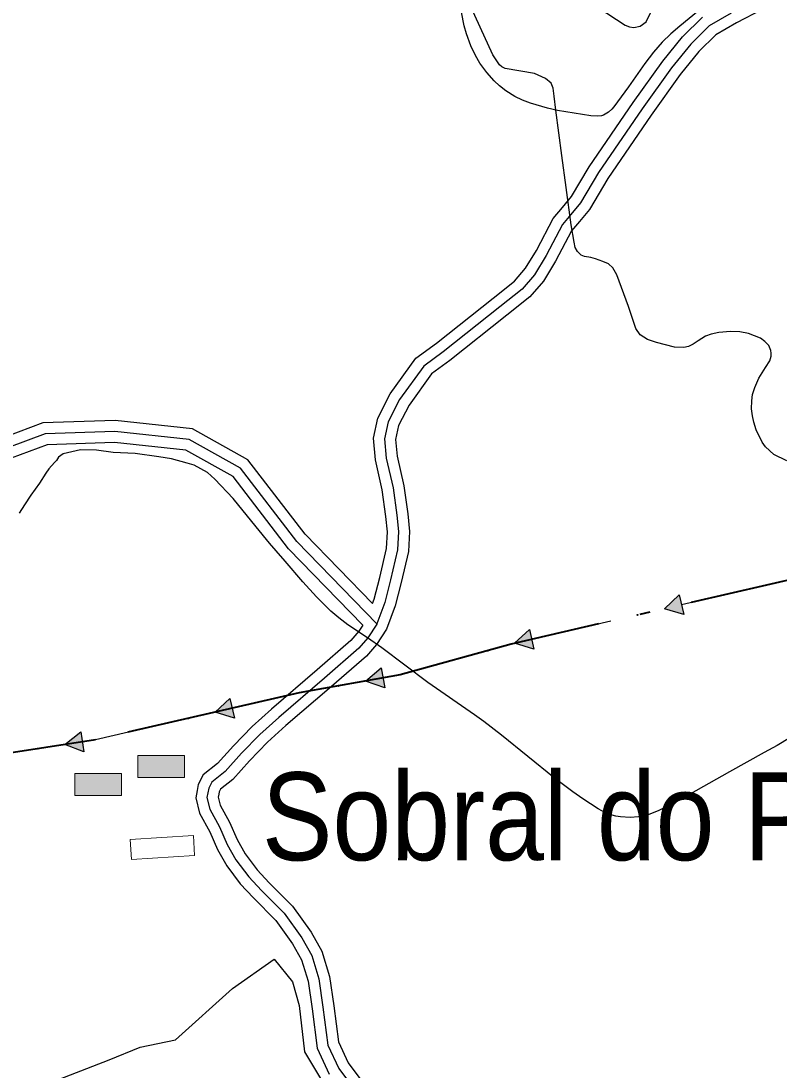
# Model space of a CAD drawing. Extents: x -64005 to -55000, y -89025 to -80000.
# Drawn here: x -60437 to -59747, y -83126 to -82170 of the extents above; entities that cross this region are included whole.
import ezdxf
from ezdxf.enums import TextEntityAlignment as Align

# ---------------------------------------------------------------- set-up
doc = ezdxf.new("R2010")
doc.units = 0
doc.header["$LTSCALE"] = 32
doc.linetypes.add('DOT_DASHED', pattern=[7.7, 5, -1.2, 0.3, -1.2])
doc.linetypes.add('LONG_DASHED', pattern=[7.5, 6, -1.5])
for name, color, linetype, lineweight in [('18', 7, 'Continuous', 25), ('24', 7, 'Continuous', 25), ('39', 7, 'LONG_DASHED', 25), ('7', 7, 'Continuous', 13), ('8', 7, 'Continuous', 25)]:
    doc.layers.add(name, color=color, linetype=linetype, lineweight=lineweight)
doc.layers.add('45', color=7, linetype='Continuous')

msp = doc.modelspace()

# ---------------------------------------------------------------- hatches: boundary and pattern name
at = {"layer": '18'}
for points in [[(-59833.76, -82710.63), (-59851.45, -82705.23), (-59837.92, -82692.61)], [(-59970.17, -82742.14), (-59987.86, -82736.73), (-59974.33, -82724.11)], [(-60106.08, -82777.3), (-60123.49, -82771.03), (-60109.35, -82759.1)], [(-60242.84, -82804.89), (-60260.53, -82799.46), (-60246.98, -82786.86)], [(-60380.13, -82835.48), (-60397.37, -82828.75), (-60382.93, -82817.19)]]:
    msp.add_hatch(color=256, dxfattribs=at).paths.add_polyline_path(points)
at = {"layer": '7'}
for points in [[(-60288.31, -82838.97), (-60330.81, -82838.97), (-60330.81, -82858.97), (-60288.31, -82858.97)], [(-60345.88, -82855.27), (-60388.38, -82855.27), (-60388.38, -82875.27), (-60345.88, -82875.27)]]:
    msp.add_hatch(color=256, dxfattribs=at).paths.add_polyline_path(points)

# ---------------------------------------------------------------- linework, layer by layer
at = {"layer": '18'}
for p, q in [((-59763.76, -82684.97), (-59835.84, -82701.62)), ((-59900.17, -82716.48), (-59972.25, -82733.12))]:
    msp.add_line(p, q, dxfattribs=at)
at = {"layer": '18', "linetype": 'DOT_DASHED', "lineweight": 40}
msp.add_lwpolyline([(-59415, -82487.84), (-59547.04, -82633.44), (-59552.52, -82637.79), (-59671.25, -82663.61), (-59990.81, -82737.41), (-60092.11, -82765.4), (-60184.07, -82781.9), (-60369.54, -82824.5), (-60744.45, -82882.06)], dxfattribs=at)
at = {"layer": '18'}
for points in [[(-59833.76, -82710.63), (-59851.45, -82705.23), (-59837.92, -82692.61)], [(-59970.17, -82742.14), (-59987.86, -82736.73), (-59974.33, -82724.11)], [(-60106.08, -82777.3), (-60123.49, -82771.03), (-60109.35, -82759.1)], [(-60242.84, -82804.89), (-60260.53, -82799.46), (-60246.98, -82786.86)], [(-60380.13, -82835.48), (-60397.37, -82828.75), (-60382.93, -82817.19)]]:
    msp.add_lwpolyline(points, close=True, dxfattribs=at)
for points in [[(-60036.09, -82749.92), (-60092.11, -82765.4), (-60107.72, -82768.2)], [(-60172.7, -82779.86), (-60184.07, -82781.9), (-60244.91, -82795.87)], [(-60309.26, -82810.65), (-60369.54, -82824.5), (-60381.53, -82826.33)]]:
    msp.add_lwpolyline(points, dxfattribs=at)
for centre in [(-59875.81, -82710.85), (-60011.99, -82743.26), (-60148.09, -82775.45), (-60284.89, -82805.06), (-60422.08, -82832.53)]:
    msp.add_circle(centre, 0.5, dxfattribs=at)
at = {"layer": '24'}
msp.add_lwpolyline([(-59820.41, -82161.05), (-59837.35, -82174.85), (-59845.51, -82181.99), (-59853.29, -82189.56), (-59861.23, -82198.55), (-59869.17, -82208.88), (-59884.17, -82230.19), (-59897.5, -82248.39), (-59899.25, -82250.46), (-59902.31, -82253.29), (-59906.86, -82255.9), (-59908.73, -82256.48), (-59912.56, -82257.02), (-59918.43, -82256.66), (-59948.62, -82251.64), (-59957.84, -82249.55), (-59973.2, -82245.1), (-59980.53, -82242.32), (-59987.66, -82238.92), (-59995.77, -82233.89), (-60001.44, -82229.43), (-60006.47, -82224.69), (-60013.15, -82217.21), (-60019.36, -82208.69), (-60023.5, -82201.72), (-60027.74, -82192.84), (-60031.66, -82181.96), (-60033.65, -82174.61), (-60036.09, -82162.18)], dxfattribs=at)
at = {"layer": '39'}
for points in [[(-59790.53, -82163.21), (-59810.54, -82174.76), (-59827.44, -82191.38), (-59844.91, -82212.8), (-59871.66, -82250.26), (-59911.37, -82308.29), (-59927.71, -82335.9), (-59936.45, -82346.33), (-59944.34, -82355.62), (-59958.99, -82383.79)], [(-59958.99, -82383.79), (-59969.69, -82401.26), (-59980.96, -82414.22), (-60001.24, -82430.29), (-60052.78, -82471.42), (-60070.54, -82484.38), (-60092.51, -82514.81), (-60102.94, -82535.09), (-60106.32, -82550.58), (-60104.63, -82568.04), (-60098.43, -82595.08), (-60095.05, -82620.15), (-60093.64, -82635.08), (-60094.48, -82651.7), (-60100.96, -82679.02), (-60106.03, -82699.59), (-60113.2, -82718.88)], [(-60113.2, -82718.88), (-60186.18, -82644.05), (-60237.35, -82577.3), (-60284.06, -82551.23), (-60351.91, -82543.94), (-60415.31, -82546.03), (-60448.68, -82558.55), (-60477.6, -82562.73), (-60498.07, -82569.45)], [(-60113.2, -82718.88), (-60113.36, -82719.3), (-60121.53, -82731.7), (-60129.69, -82741.28), (-60160.95, -82768.34), (-60202.65, -82804.12), (-60219.83, -82819.61), (-60236.45, -82836.79), (-60251.37, -82853.42), (-60263.49, -82863), (-60266.3, -82868.63), (-60267.99, -82877.08), (-60265.46, -82887.79), (-60256.45, -82903.84), (-60249.4, -82919.9), (-60241.52, -82933.7), (-60229.97, -82949.18), (-60218.42, -82961.57), (-60197.58, -82982.42), (-60181.52, -83004.95), (-60172.51, -83021.01), (-60166.03, -83042.13), (-60162.37, -83068.05), (-60157.86, -83102.41), (-60148, -83123.82), (-60136.45, -83139.31)]]:
    msp.add_lwpolyline(points, dxfattribs=at)
at = {"layer": '7', "lineweight": 25}
for points in [[(-59945.03, -82135.71), (-59887.11, -82173.96), (-59883.25, -82175.62), (-59879.2, -82176.17), (-59873.32, -82174.88), (-59867.99, -82171.02), (-59846.48, -82126.5)], [(-59754.16, -82472.65), (-59754.35, -82470.26), (-59756.37, -82465.66), (-59759.86, -82461.98), (-59763.91, -82459.04), (-59774.94, -82454.81), (-59782.85, -82453.16), (-59791.3, -82452.79), (-59801.97, -82453.71), (-59808.95, -82455.18), (-59814.1, -82457.21), (-59820.53, -82461.44), (-59825.13, -82464.57), (-59829.54, -82466.41), (-59833.59, -82467.51), (-59842.23, -82467.14), (-59858.59, -82462.92), (-59866.68, -82460.16), (-59873.48, -82455.93), (-59877.34, -82450.23), (-59884.15, -82429.99), (-59894.82, -82401.3), (-59898.3, -82395.05), (-59902.35, -82391.37), (-59907.31, -82389.17), (-59914.11, -82386.78), (-59918.53, -82385.67), (-59924.04, -82384.75), (-59927.17, -82383.47), (-59930.66, -82379.97), (-59932.68, -82376.48), (-59933.6, -82371.7), (-59936.18, -82355.88), (-59940.78, -82321.85), (-59944.82, -82292.61), (-59950.16, -82251.41), (-59951.82, -82238.71), (-59952.73, -82231.36), (-59954.57, -82226.94), (-59959.54, -82222.71), (-59969.65, -82218.12), (-59996.31, -82213.52), (-59999.43, -82211.87), (-60001.64, -82210.03), (-60007.53, -82201.02), (-60030.7, -82150.44)], [(-59739.82, -82570.68), (-59751.77, -82564.8), (-59759.31, -82557.99), (-59762.25, -82553.58), (-59767.95, -82542.54), (-59769.97, -82535.55), (-59771.26, -82529.67), (-59772, -82523.41), (-59771.81, -82516.06), (-59771.08, -82510.17), (-59769.06, -82503.73), (-59765.38, -82495.27), (-59759.32, -82485.52), (-59755.45, -82479.46), (-59754.16, -82475.41), (-59754.16, -82472.65)], [(-60204.9, -82652.61), (-60211.11, -82645.41), (-60223, -82630.64), (-60244.09, -82604.94), (-60260.92, -82587.3), (-60267.56, -82581.33), (-60273.57, -82577.76), (-60279.63, -82574.62), (-60285.9, -82572.74), (-60300.22, -82568.7), (-60311.68, -82566.85), (-60333.38, -82564.05), (-60353.49, -82562.99), (-60368.52, -82561.06), (-60383.21, -82560.59), (-60399.04, -82564.1), (-60403.02, -82567.37), (-60405.01, -82570.36), (-60406.82, -82572.16), (-60411.84, -82577.85), (-60414.57, -82581.7), (-60420.57, -82590.92), (-60428.43, -82601.9), (-60434.11, -82610.63), (-60439.05, -82618.21)], [(-59725.79, -82815.8), (-59748.81, -82829.62), (-59760.44, -82836.09), (-59792.21, -82853.66), (-59834.46, -82877.64), (-59856.99, -82889.16), (-59865.45, -82892.46), (-59871.17, -82893.9), (-59875, -82894.55), (-59882.61, -82895.17), (-59891.3, -82894.73), (-59895.66, -82893.97), (-59902.15, -82892.1), (-59908.52, -82889.27), (-59911.65, -82887.46), (-59925.8, -82878.19), (-59934.76, -82871.89), (-59951.8, -82859.09), (-59999.67, -82820.43), (-60015.97, -82807.96), (-60024.43, -82801.89), (-60066.85, -82772.49), (-60108.71, -82740.82), (-60121.82, -82731.75), (-60139.52, -82719.91), (-60148.01, -82713.45), (-60155.04, -82707.38), (-60168.26, -82694.41), (-60180.7, -82680.69), (-60196.79, -82661.92), (-60204.9, -82652.61)], [(-60442.25, -83149), (-60357.08, -83115.93), (-60328.72, -83104.33), (-60296.72, -83097.67), (-60244.72, -83050.98), (-60206.75, -83024.23), (-60190.06, -83044.98), (-60184.06, -83066.32), (-60179.27, -83108.43), (-60157.27, -83145.11), (-59990.07, -83313.07), (-59940.9, -83370.88), (-59895.07, -83431.4), (-59830.9, -83589.14), (-59796.07, -83726.7), (-59788.35, -83775.32), (-59799.58, -83809.66)]]:
    msp.add_lwpolyline(points, dxfattribs=at)
at = {"layer": '7'}
for points in [[(-60288.31, -82838.97), (-60330.81, -82838.97), (-60330.81, -82858.97), (-60288.31, -82858.97)], [(-60345.88, -82855.27), (-60388.38, -82855.27), (-60388.38, -82875.27), (-60345.88, -82875.27)], [(-60337.84, -82915.22), (-60280.32, -82911.62), (-60279.18, -82929.95), (-60336.7, -82933.55)]]:
    msp.add_lwpolyline(points, close=True, dxfattribs=at)
at = {"layer": '8'}
for points in [[(-59655.23, -82161.61), (-59656.94, -82162.66), (-59668.05, -82164.25), (-59687.69, -82162.38), (-59708.82, -82157.25), (-59731.23, -82153.82), (-59748.53, -82155.05), (-59762.36, -82159.75), (-59785.71, -82171.97), (-59804.43, -82182.78), (-59820.04, -82198.13), (-59836.96, -82218.87), (-59863.46, -82255.99), (-59902.93, -82313.67), (-59919.52, -82341.7), (-59928.8, -82352.78), (-59935.99, -82361.23), (-59950.46, -82389.01)], [(-59950.46, -82389.01), (-59961.6, -82407.19), (-59974.03, -82421.48), (-59995.02, -82438.11), (-60046.71, -82479.37), (-60063.36, -82491.52), (-60083.96, -82520.05), (-60093.45, -82538.5), (-60096.22, -82551.18), (-60094.74, -82566.43), (-60088.58, -82593.29), (-60085.11, -82619.01), (-60083.62, -82634.85), (-60084.54, -82653.11), (-60091.24, -82681.37), (-60096.46, -82702.54), (-60104.38, -82723.85), (-60113.52, -82737.72), (-60122.57, -82748.34), (-60154.42, -82775.91), (-60196.05, -82811.63), (-60212.88, -82826.81), (-60229.13, -82843.61), (-60244.5, -82860.74), (-60255.54, -82869.46), (-60256.76, -82871.9), (-60257.16, -82873.88)], [(-60125.91, -82720.16), (-60193.77, -82650.61), (-60244.03, -82585.02), (-60287.15, -82560.95), (-60352.28, -82553.96), (-60413.34, -82555.97), (-60446.18, -82568.29), (-60475.31, -82572.5), (-60494.11, -82578.67), (-60511.7, -82598.84), (-60542.4, -82651.29), (-60595.95, -82740.21), (-60633.26, -82795.8), (-60645.47, -82828.02), (-60664.27, -82857.42), (-60679.76, -82864.68), (-60701.53, -82865.95), (-60726.57, -82856.83), (-60732.06, -82848.6)], [(-60257.16, -82873.88), (-60257.76, -82876.9), (-60256.05, -82884.12), (-60247.49, -82899.37), (-60240.45, -82915.4), (-60233.14, -82928.2), (-60222.28, -82942.76), (-60211.22, -82954.62), (-60189.92, -82975.94), (-60173.06, -82999.59), (-60163.26, -83017.05), (-60156.24, -83039.95), (-60152.46, -83066.7), (-60148.14, -83099.6), (-60139.36, -83118.68), (-60128.88, -83132.73)]]:
    msp.add_lwpolyline(points, dxfattribs=at)
at = {"layer": '8', "linetype": 'LONG_DASHED'}
for points in [[(-59967.54, -82378.56), (-59952.69, -82350.01), (-59944.09, -82339.88), (-59935.91, -82330.11), (-59919.81, -82302.91), (-59879.86, -82244.53), (-59852.86, -82206.73), (-59834.84, -82184.63), (-59816.64, -82166.74)], [(-60117.07, -82700.58), (-60115.6, -82696.64), (-60110.68, -82676.67), (-60104.42, -82650.29), (-60103.66, -82635.31), (-60104.99, -82621.29), (-60108.28, -82596.87), (-60114.52, -82569.65), (-60116.42, -82549.98), (-60112.43, -82531.68), (-60101.06, -82509.57), (-60077.72, -82477.24), (-60058.85, -82463.47), (-60007.46, -82422.46), (-59987.89, -82406.97), (-59977.78, -82395.34), (-59967.88, -82379.17), (-59967.67, -82378.82), (-59967.54, -82378.56)], [(-60117.07, -82700.58), (-60178.6, -82637.48), (-60230.67, -82569.58), (-60280.97, -82541.51), (-60351.54, -82533.92), (-60417.28, -82536.09), (-60451.18, -82548.81), (-60479.89, -82552.96), (-60492.22, -82557)], [(-60125.91, -82720.16), (-60129.54, -82725.68), (-60136.81, -82734.21), (-60167.49, -82760.76), (-60209.25, -82796.61), (-60226.78, -82812.41), (-60243.77, -82829.98), (-60258.24, -82846.1), (-60271.44, -82856.54), (-60275.84, -82865.36), (-60276.89, -82870.61)], [(-60276.89, -82870.61), (-60278.22, -82877.26), (-60274.87, -82891.46), (-60265.41, -82908.31), (-60258.35, -82924.4), (-60249.9, -82939.19), (-60237.66, -82955.6), (-60225.62, -82968.52), (-60205.24, -82988.9), (-60189.98, -83010.31), (-60181.76, -83024.97), (-60175.82, -83044.31), (-60172.28, -83069.4), (-60167.58, -83105.22), (-60156.64, -83128.96)]]:
    msp.add_lwpolyline(points, dxfattribs=at)

# ---------------------------------------------------------------- texts
at = {"layer": '45', "width": 0.9}
msp.add_text('Sobral do Porto Seixo', height=80, rotation=0.007, dxfattribs=at).set_placement((-59749.62, -82934.14), align=Align.CENTER)

doc.saveas('drawing.dxf')
